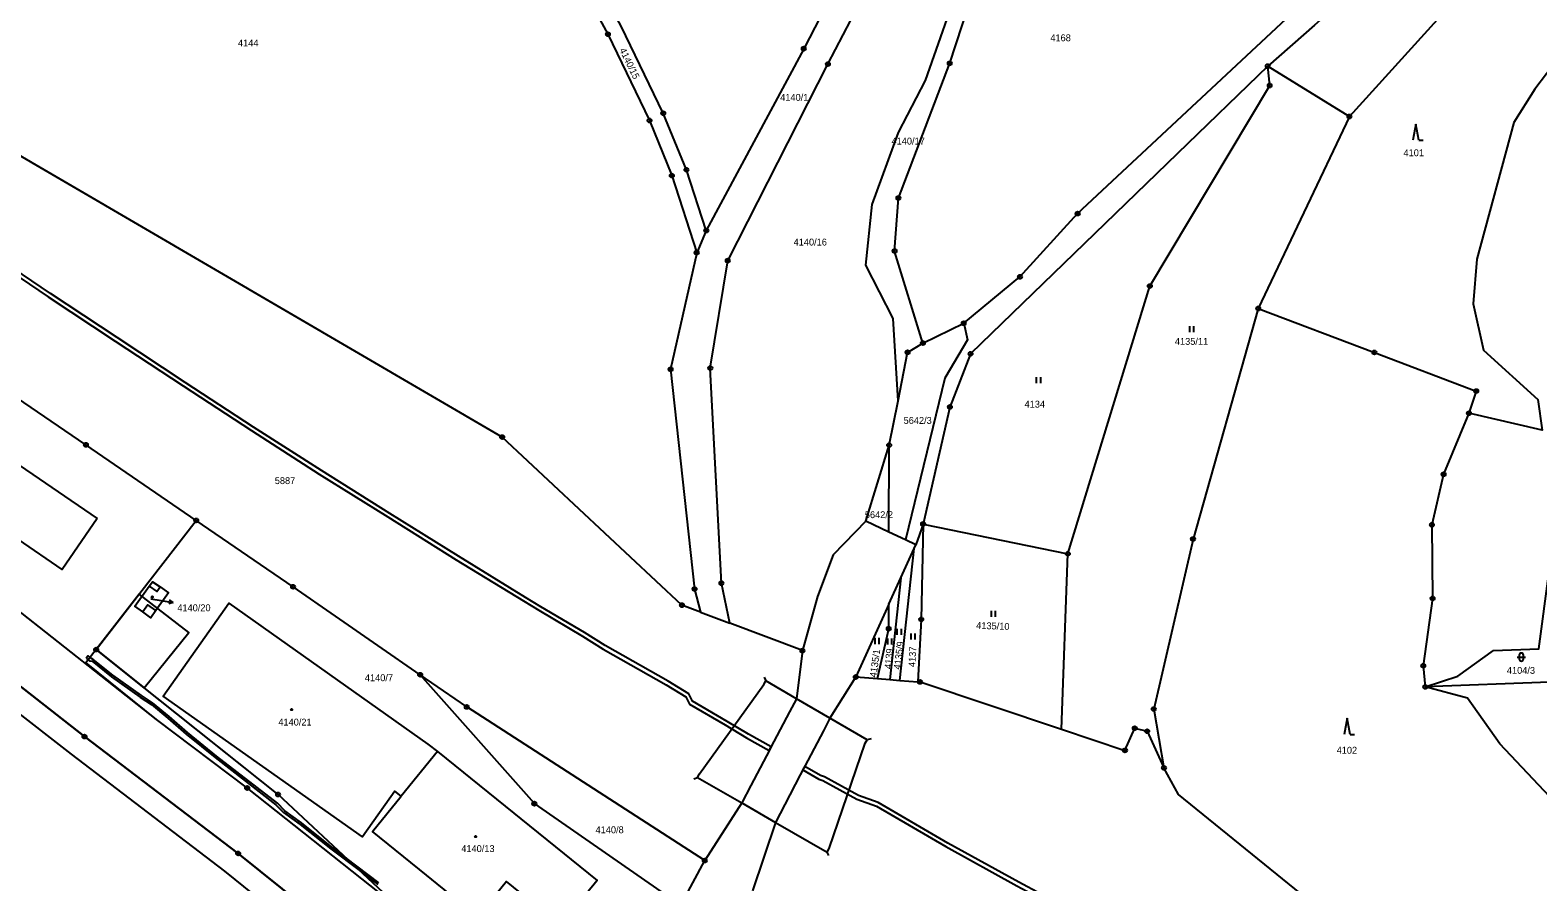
# Model space of a CAD drawing. Extents: x -644096 to -634268, y -1141430 to -1133463.
# Drawn here: x -641187.5 to -640815.2, y -1136928.3 to -1136718.2 of the extents above; entities that cross this region are included whole.
import ezdxf

# ---------------------------------------------------------------- set-up
doc = ezdxf.new("R2010")
doc.units = 0
for name, color, linetype in [('_CIVIL_CONSTRUCTION', 7, 'Continuous'), ('B_Hranice _3D', 7, 'Continuous'), ('M_Svah_Nasyp', 7, 'Continuous'), ('M_Svah_Zarez', 7, 'Continuous'), ('svrsek_osa_sjezdy', 7, 'Continuous'), ('svrsek_osa_VRT', 7, 'Continuous'), ('svrsek_popisy_VRT', 7, 'Continuous'), ('terminal_VRT', 7, 'Continuous')]:
    doc.layers.add(name, color=color, linetype=linetype)

msp = doc.modelspace()

# ---------------------------------------------------------------- linework, layer by layer
at = {"layer": '_CIVIL_CONSTRUCTION'}
for centre, radius in [((-641044.81, -1136719.17), 0.5), ((-641044.81, -1136719.17), 0.0303), ((-640996.46, -1136722.74), 0.5), ((-640996.46, -1136722.74), 0.0303), ((-640990.48, -1136726.55), 0.5), ((-640990.48, -1136726.55), 0.0303), ((-640960.4, -1136726.35), 0.5), ((-640960.4, -1136726.35), 0.0303), ((-640881.86, -1136727.05), 0.5), ((-640881.86, -1136727.05), 0.0303), ((-640881.37, -1136731.83), 0.5), ((-640881.37, -1136731.83), 0.0303), ((-641034.54, -1136740.46), 0.5), ((-641034.54, -1136740.46), 0.0303), ((-641031.14, -1136738.67), 0.5), ((-641031.14, -1136738.67), 0.0303), ((-640861.71, -1136739.47), 0.5), ((-640861.71, -1136739.47), 0.0303), ((-641025.42, -1136752.63), 0.5), ((-641025.42, -1136752.63), 0.0303), ((-641029.02, -1136754.05), 0.5), ((-641029.02, -1136754.05), 0.0303), ((-640973.07, -1136759.6), 0.5), ((-640973.07, -1136759.6), 0.0303), ((-640928.81, -1136763.44), 0.5), ((-640928.81, -1136763.44), 0.0303), ((-641020.51, -1136767.62), 0.5), ((-641020.51, -1136767.62), 0.0303), ((-641022.89, -1136773.08), 0.5), ((-641022.89, -1136773.08), 0.0303), ((-641015.22, -1136775.06), 0.5), ((-641015.22, -1136775.06), 0.0303), ((-640974.02, -1136772.68), 0.5), ((-640974.02, -1136772.68), 0.0303), ((-640943.05, -1136779.05), 0.5), ((-640943.05, -1136779.05), 0.0303), ((-640910.99, -1136781.33), 0.5), ((-640910.99, -1136781.33), 0.0303), ((-640884.2, -1136786.86), 0.5), ((-640884.2, -1136786.86), 0.0303), ((-640956.95, -1136790.5), 0.5), ((-640956.95, -1136790.5), 0.0303), ((-640970.81, -1136797.68), 0.5), ((-640967.02, -1136795.4), 0.5), ((-640967.02, -1136795.4), 0.0303), ((-640855.52, -1136797.7), 0.5), ((-641019.52, -1136801.57), 0.5), ((-640970.81, -1136797.68), 0.0303), ((-640955.26, -1136798.04), 0.5), ((-640955.26, -1136798.04), 0.0303), ((-640855.52, -1136797.7), 0.0303), ((-641029.33, -1136801.85), 0.5), ((-641029.33, -1136801.85), 0.0303), ((-641019.52, -1136801.57), 0.0303), ((-640830.37, -1136807.23), 0.5), ((-640830.37, -1136807.23), 0.0303), ((-640960.36, -1136811.17), 0.5), ((-640960.36, -1136811.17), 0.0303), ((-640832.18, -1136812.7), 0.5), ((-640832.18, -1136812.7), 0.0303), ((-641070.93, -1136818.59), 0.5), ((-641070.93, -1136818.59), 0.0303), ((-641173.71, -1136820.5), 0.5), ((-641173.71, -1136820.5), 0.0303), ((-640975.35, -1136820.59), 0.5), ((-640975.35, -1136820.59), 0.0303), ((-640838.43, -1136827.76), 0.5), ((-640838.43, -1136827.76), 0.0303), ((-641146.48, -1136839.16), 0.5), ((-641146.48, -1136839.16), 0.0303), ((-640966.99, -1136840.04), 0.5), ((-640966.99, -1136840.04), 0.0303), ((-640841.33, -1136840.25), 0.5), ((-640841.33, -1136840.25), 0.0303), ((-640900.32, -1136843.75), 0.5), ((-640900.32, -1136843.75), 0.0303), ((-640931.24, -1136847.39), 0.5), ((-640931.24, -1136847.39), 0.0303), ((-641122.56, -1136855.53), 0.5), ((-641122.56, -1136855.53), 0.0303), ((-641023.42, -1136856.09), 0.5), ((-641023.42, -1136856.09), 0.0303), ((-641016.78, -1136854.64), 0.5), ((-641016.78, -1136854.64), 0.0303), ((-641026.53, -1136860.06), 0.5), ((-641026.53, -1136860.06), 0.0303), ((-640841.16, -1136858.41), 0.5), ((-640841.16, -1136858.41), 0.0303), ((-640967.44, -1136863.59), 0.5), ((-640967.44, -1136863.59), 0.0303), ((-640975.46, -1136865.87), 0.5), ((-640975.46, -1136865.87), 0.0303), ((-641171.19, -1136871.04), 0.5), ((-641171.19, -1136871.04), 0.0303), ((-640996.78, -1136871.28), 0.5), ((-640996.78, -1136871.28), 0.0303), ((-640843.46, -1136875.03), 0.5), ((-640843.46, -1136875.03), 0.0303), ((-641091.18, -1136877.23), 0.5), ((-641091.18, -1136877.23), 0.0303), ((-640983.59, -1136877.79), 0.5), ((-640983.59, -1136877.79), 0.0303), ((-640967.72, -1136879.01), 0.5), ((-640967.72, -1136879.01), 0.0303), ((-640842.96, -1136880.23), 0.5), ((-640842.96, -1136880.23), 0.0303), ((-641079.67, -1136885.18), 0.5), ((-641079.67, -1136885.18), 0.0303), ((-640910.01, -1136885.72), 0.5), ((-640910.01, -1136885.72), 0.0303), ((-640914.71, -1136890.43), 0.5), ((-640914.71, -1136890.43), 0.0303), ((-641174.07, -1136892.51), 0.5), ((-641174.07, -1136892.51), 0.0303), ((-640911.64, -1136891.17), 0.5), ((-640911.64, -1136891.17), 0.0303), ((-640917.12, -1136895.9), 0.5), ((-640917.12, -1136895.9), 0.0303), ((-640907.49, -1136900.22), 0.5), ((-640907.49, -1136900.22), 0.0303), ((-641133.9, -1136905.19), 0.5), ((-641133.9, -1136905.19), 0.0303), ((-641126.26, -1136906.79), 0.5), ((-641126.26, -1136906.79), 0.0303), ((-641062.98, -1136909.05), 0.5), ((-641062.98, -1136909.05), 0.0303), ((-641136.12, -1136921.34), 0.5), ((-641136.12, -1136921.34), 0.0303), ((-641020.89, -1136923.11), 0.5), ((-641020.89, -1136923.11), 0.0303)]:
    msp.add_circle(centre, radius, dxfattribs=at)
at = {"layer": 'B_Hranice _3D'}
for points in [[(-641199.5, -1136772.91), (-641183.01, -1136784.01), (-641166.53, -1136794.89), (-641149.71, -1136805.97), (-641132.85, -1136816.95), (-641116.09, -1136827.7), (-641099.17, -1136838.31), (-641082.25, -1136848.86), (-641065.66, -1136859.01), (-641061.89, -1136861.31), (-641051.1, -1136867.71), (-641045.99, -1136870.9), (-641030.45, -1136879.69), (-641025.57, -1136882.66), (-641024.65, -1136884.48), (-641015.89, -1136889.63), (-641010.59, -1136892.79), (-641007.77, -1136894.33), (-641004.98, -1136895.94), (-641004.51, -1136895.05), (-641007.29, -1136893.45), (-641010.09, -1136891.93), (-641015.39, -1136888.77), (-641023.89, -1136883.76), (-641024.81, -1136881.96), (-641029.95, -1136878.83), (-641045.47, -1136870.04), (-641050.58, -1136866.85), (-641061.37, -1136860.45), (-641065.14, -1136858.15), (-641081.73, -1136848), (-641098.63, -1136837.47), (-641115.55, -1136826.86), (-641132.31, -1136816.11), (-641149.17, -1136805.13), (-641165.97, -1136794.05), (-641182.45, -1136783.17), (-641198.94, -1136772.09)], [(-640932.27, -1136934.34), (-640943.37, -1136928.42), (-640960.83, -1136918.76), (-640978.07, -1136908.79), (-640982.89, -1136907.05), (-640991.35, -1136902.42), (-640992.34, -1136902.08), (-640996.21, -1136899.85), (-640996.67, -1136900.74), (-640992.76, -1136903), (-640991.75, -1136903.34), (-640983.31, -1136907.97), (-640978.49, -1136909.71), (-640961.33, -1136919.64), (-640943.85, -1136929.3), (-640932.75, -1136935.22), (-640926.3, -1136938.9), (-640908.7, -1136948.23), (-640890.7, -1136957.63), (-640873.12, -1136966.73), (-640855.28, -1136975.78), (-640837.3, -1136984.75), (-640819.52, -1136993.48), (-640801.34, -1137002.18)], [(-641101.36, -1136928.56), (-641109.5, -1136922.41), (-641105.94, -1136925.72), (-641101.66, -1136928.96)]]:
    msp.add_lwpolyline(points, dxfattribs=at)
for points in [[(-641263.85, -1136833.08), (-641242.49, -1136847.34), (-641207.87, -1136873.11), (-641177.38, -1136896.86), (-641139.48, -1136925.67), (-641106.26, -1136952.5), (-641103.94, -1136947.21), (-641136.12, -1136921.34), (-641174.07, -1136892.51), (-641204.56, -1136868.74), (-641239.35, -1136842.84), (-641260.66, -1136828.6)], [(-641171.19, -1136871.04), (-641159.31, -1136880.49), (-641148.32, -1136866.85), (-641160.58, -1136857.35)], [(-641173.72, -1136874.3), (-641156.38, -1136888.32), (-641133.9, -1136905.19), (-641094.12, -1136936.74), (-641126.26, -1136906.79), (-641159.31, -1136880.49), (-641171.19, -1136871.04)], [(-641173.63, -1136873.17), (-641172.8, -1136873.79), (-641172.21, -1136873.86), (-641167.38, -1136877.72), (-641160.3, -1136882.76), (-641157.55, -1136884.6), (-641153.46, -1136887.96), (-641148.97, -1136891.91), (-641141.76, -1136897.7), (-641126.78, -1136909.32), (-641124.95, -1136911.23), (-641120.8, -1136914.21), (-641113.25, -1136920.2), (-641105.94, -1136925.72), (-641109.5, -1136922.41), (-641112.95, -1136919.8), (-641120.5, -1136913.81), (-641124.63, -1136910.85), (-641126.44, -1136908.94), (-641141.46, -1136897.3), (-641148.65, -1136891.53), (-641153.14, -1136887.58), (-641157.25, -1136884.2), (-641160.02, -1136882.34), (-641167.08, -1136877.32), (-641171.95, -1136873.44), (-641172.35, -1136873.19), (-641173.18, -1136872.57)]]:
    msp.add_lwpolyline(points, close=True, dxfattribs=at)
at = {"layer": 'M_Svah_Nasyp'}
for p, q in [((-641006.26, -1136877.87), (-641005.82, -1136878.77)), ((-640998.26, -1136883.15), (-641005.82, -1136878.77)), ((-640989.98, -1136887.93), (-640998.26, -1136883.15)), ((-640980.75, -1136893.26), (-640989.98, -1136887.93)), ((-640979.77, -1136893.09), (-640980.75, -1136893.26)), ((-641023.63, -1136902.95), (-641022.71, -1136902.56)), ((-641022.71, -1136902.56), (-641011.76, -1136908.86)), ((-641011.76, -1136908.86), (-641003.42, -1136913.67)), ((-641003.42, -1136913.67), (-640990.7, -1136920.99)), ((-640990.23, -1136921.87), (-640990.7, -1136920.99))]:
    msp.add_line(p, q, dxfattribs=at)
for points in [[(-641158.08, -1136855.36), (-641156.2, -1136856.72), (-641155.4, -1136855.58)], [(-641156.47, -1136861.4), (-641158.42, -1136860), (-641159.67, -1136861.74)], [(-641022.71, -1136902.56), (-641022.21, -1136901.69), (-641006.32, -1136879.63), (-641005.82, -1136878.77)], [(-640990.7, -1136920.99), (-640990.2, -1136920.12), (-640981.25, -1136894.12), (-640980.75, -1136893.26)]]:
    msp.add_lwpolyline(points, dxfattribs=at)
at = {"layer": 'M_Svah_Zarez'}
for centre in [(-641157.33, -1136858.03), (-641122.94, -1136885.82), (-641077.49, -1136917.17)]:
    msp.add_circle(centre, 0.175, dxfattribs=at)
at = {"layer": 'svrsek_osa_sjezdy'}
for p, q in [((-640845.27, -1136741.35), (-640846.02, -1136745.35)), ((-640844.52, -1136745.35), (-640845.27, -1136741.35)), ((-640844.52, -1136745.35), (-640843.52, -1136745.35)), ((-640901.1, -1136792.7), (-640901.1, -1136791.2)), ((-640900.1, -1136792.7), (-640900.1, -1136791.2)), ((-640938.94, -1136805.28), (-640938.94, -1136803.78)), ((-640937.94, -1136805.28), (-640937.94, -1136803.78)), ((-640950.12, -1136862.93), (-640950.12, -1136861.43)), ((-640949.12, -1136862.93), (-640949.12, -1136861.43)), ((-640978.82, -1136869.66), (-640978.82, -1136868.16)), ((-640977.82, -1136869.66), (-640977.82, -1136868.16)), ((-640973.35, -1136867.39), (-640973.35, -1136865.89)), ((-640972.35, -1136867.39), (-640972.35, -1136865.89)), ((-640969.95, -1136868.56), (-640969.95, -1136867.06)), ((-640968.95, -1136868.56), (-640968.95, -1136867.06)), ((-640975.67, -1136869.8), (-640975.67, -1136868.3)), ((-640974.67, -1136869.8), (-640974.67, -1136868.3)), ((-640820.24, -1136872.88), (-640818.24, -1136872.88)), ((-640819.74, -1136872.38), (-640819.74, -1136873.38)), ((-640818.74, -1136873.38), (-640818.74, -1136872.38)), ((-640862.23, -1136887.99), (-640862.98, -1136891.99)), ((-640861.48, -1136891.99), (-640862.23, -1136887.99)), ((-640861.48, -1136891.99), (-640860.48, -1136891.99))]:
    msp.add_line(p, q, dxfattribs=at)
for centre, start, end in [((-640819.24, -1136872.38), 0, 180), ((-640819.24, -1136873.38), 180, 359.9879)]:
    msp.add_arc(centre, 0.5, start, end, dxfattribs=at)
at = {"layer": 'svrsek_popisy_VRT'}
for p, q in [((-641157.68, -1136858.48), (-641155.15, -1136858.91)), ((-641155.15, -1136858.91), (-641152.2, -1136859.43)), ((-641152.2, -1136859.43), (-641153.27, -1136859.75)), ((-641152.2, -1136859.43), (-641153.09, -1136858.76))]:
    msp.add_line(p, q, dxfattribs=at)
at = {"layer": 'terminal_VRT'}
for p, q in [((-640881.86, -1136727.05), (-640861.71, -1136739.47)), ((-640861.71, -1136739.47), (-640884.2, -1136786.86)), ((-641020.51, -1136767.62), (-641022.89, -1136773.08)), ((-640967.02, -1136795.4), (-640956.95, -1136790.5)), ((-640975.35, -1136820.59), (-640973.1, -1136809.65)), ((-640981.08, -1136839.37), (-640975.35, -1136820.59)), ((-640975.4, -1136842.05), (-640975.35, -1136820.59)), ((-640975.4, -1136842.05), (-640981.08, -1136839.37)), ((-640971.32, -1136843.97), (-640975.4, -1136842.05)), ((-640966.99, -1136840.04), (-640968.78, -1136845.17)), ((-640966.99, -1136840.04), (-640931.24, -1136847.39)), ((-640968.78, -1136845.17), (-640971.32, -1136843.97)), ((-640969.18, -1136846.05), (-640968.78, -1136845.17)), ((-640972.48, -1136853.31), (-640969.18, -1136846.05)), ((-640932.82, -1136890.66), (-640931.24, -1136847.39)), ((-640975.45, -1136859.85), (-640972.48, -1136853.31)), ((-640972.48, -1136853.31), (-640975.22, -1136878.43)), ((-640975.45, -1136859.85), (-640983.59, -1136877.79)), ((-641021.98, -1136861.78), (-641014.71, -1136864.52)), ((-640996.78, -1136871.28), (-641014.71, -1136864.52)), ((-640983.59, -1136877.79), (-640978.21, -1136878.2)), ((-640978.21, -1136878.2), (-640975.22, -1136878.43)), ((-640975.22, -1136878.43), (-640972.74, -1136878.62)), ((-640972.74, -1136878.62), (-640968.3, -1136878.97)), ((-640812.31, -1136879.11), (-640842.96, -1136880.23)), ((-641086.91, -1136896.17), (-641095.88, -1136907.22)), ((-641026.83, -1136934.12), (-641020.89, -1136923.11))]:
    msp.add_line(p, q, dxfattribs=at)
for points in [[(-640825.4, -1136677.24), (-640870.35, -1136716.9), (-640881.86, -1136727.05)], [(-640973.1, -1136809.65), (-640974.34, -1136789.33), (-640981.09, -1136776.14), (-640979.53, -1136761.22), (-640973.02, -1136743.42), (-640966.4, -1136730.6), (-640948.09, -1136678.55)], [(-640967.02, -1136795.4), (-640974.02, -1136772.68), (-640973.07, -1136759.6), (-640960.4, -1136726.35), (-640945.05, -1136679.55)], [(-640814.44, -1136685.07), (-640836.78, -1136712.1), (-640861.71, -1136739.47)], [(-640785.47, -1136686.87), (-640810.18, -1136725.16), (-640815.93, -1136732.72), (-640821.1, -1136740.93), (-640830.26, -1136774.68), (-640831.11, -1136785.71), (-640828.55, -1136797.1), (-640815.18, -1136809.28), (-640814.09, -1136816.89), (-640832.18, -1136812.7)], [(-641021.98, -1136861.78), (-641026.53, -1136860.06), (-641070.93, -1136818.59), (-641196.36, -1136745.52), (-641265.5, -1136695.04)], [(-641057.54, -1136696.34), (-641056.64, -1136697.54), (-641044.81, -1136719.17), (-641034.54, -1136740.46), (-641029.02, -1136754.05), (-641022.89, -1136773.08)], [(-641020.51, -1136767.62), (-641025.42, -1136752.63), (-641031.14, -1136738.67), (-641041.5, -1136717.18), (-641053.16, -1136695.94), (-641054.14, -1136694.56)], [(-640984.13, -1136698.91), (-640996.46, -1136722.74), (-641020.51, -1136767.62)], [(-641014.71, -1136864.52), (-641016.78, -1136854.64), (-641019.52, -1136801.57), (-641015.22, -1136775.06), (-640990.48, -1136726.55), (-640977.24, -1136701.11)], [(-640956.95, -1136790.5), (-640943.05, -1136779.05), (-640928.81, -1136763.44), (-640869.89, -1136708.4)], [(-640881.86, -1136727.05), (-640904.14, -1136748.6), (-640955.26, -1136798.04), (-640960.36, -1136811.17), (-640966.99, -1136840.04)], [(-640931.24, -1136847.39), (-640910.99, -1136781.33), (-640881.37, -1136731.83), (-640881.86, -1136727.05)], [(-641146.48, -1136839.16), (-641173.71, -1136820.5), (-641285.97, -1136743.98)], [(-641317.44, -1136774.35), (-641244.29, -1136822.8), (-641214.15, -1136843.74), (-641192.68, -1136859.63), (-641156.38, -1136888.32), (-641133.9, -1136905.19), (-641094.12, -1136936.74)], [(-641022.89, -1136773.08), (-641029.33, -1136801.85), (-641023.42, -1136856.09), (-641021.98, -1136861.78)], [(-641327.67, -1136787.21), (-641273.37, -1136820.11), (-641260.66, -1136828.6), (-641239.35, -1136842.84), (-641204.56, -1136868.74), (-641174.07, -1136892.51), (-641136.12, -1136921.34), (-641103.94, -1136947.21)], [(-640884.2, -1136786.86), (-640900.32, -1136843.75), (-640910.01, -1136885.72), (-640907.49, -1136900.22)], [(-640884.2, -1136786.86), (-640855.52, -1136797.7), (-640830.37, -1136807.23), (-640832.18, -1136812.7)], [(-640956.95, -1136790.5), (-640956.03, -1136794.6), (-640961.63, -1136804.07), (-640971.32, -1136843.97)], [(-640973.1, -1136809.65), (-640970.81, -1136797.68), (-640967.02, -1136795.4)], [(-641170.96, -1136838.64), (-641179.58, -1136851.27), (-641222.76, -1136821.67), (-641214.28, -1136809.16), (-641170.96, -1136838.64)], [(-640842.96, -1136880.23), (-640834.94, -1136877.62), (-640826.15, -1136871.27), (-640814.94, -1136870.88), (-640807.58, -1136815.79), (-640807.16, -1136809.05)], [(-640832.18, -1136812.7), (-640838.43, -1136827.76), (-640841.33, -1136840.25), (-640841.16, -1136858.41), (-640843.46, -1136875.03), (-640842.96, -1136880.23)], [(-641326.4, -1136920.98), (-641263.85, -1136833.08), (-641242.49, -1136847.34), (-641207.87, -1136873.11), (-641177.38, -1136896.86), (-641139.48, -1136925.67), (-641106.26, -1136952.5)], [(-641094.12, -1136936.74), (-641126.26, -1136906.79), (-641171.19, -1136871.04), (-641146.48, -1136839.16)], [(-641091.18, -1136877.23), (-641122.56, -1136855.53), (-641146.48, -1136839.16)], [(-640981.08, -1136839.37), (-640989.16, -1136847.64), (-640993.03, -1136857.91), (-640996.78, -1136871.28)], [(-640966.99, -1136840.04), (-640967.44, -1136863.59), (-640968.3, -1136878.97)], [(-640972.74, -1136878.62), (-640970.76, -1136860.52), (-640969.18, -1136846.05)], [(-641158.08, -1136855.36), (-641157.24, -1136854.28), (-641155.4, -1136855.58), (-641153.36, -1136857.04), (-641156.47, -1136861.4), (-641157.7, -1136863.16), (-641159.67, -1136861.74), (-641161.63, -1136860.34), (-641158.08, -1136855.36)], [(-641095.88, -1136907.22), (-641097.45, -1136905.94), (-641105.45, -1136917.25), (-641154.63, -1136882.5), (-641138.44, -1136859.59), (-641089.27, -1136894.35), (-641086.91, -1136896.17)], [(-640978.21, -1136878.2), (-640975.46, -1136865.87), (-640975.45, -1136859.85)], [(-640996.78, -1136871.28), (-640998.26, -1136883.15), (-640999.95, -1136886.37), (-641003.8, -1136893.69), (-641005.66, -1136897.24), (-641009.5, -1136904.55), (-641011.76, -1136908.86), (-641020.89, -1136923.11)], [(-641026.83, -1136934.12), (-641062.98, -1136909.05), (-641091.18, -1136877.23)], [(-641020.89, -1136923.11), (-641079.67, -1136885.18), (-641091.18, -1136877.23)], [(-640983.59, -1136877.79), (-640989.98, -1136887.93), (-640991.61, -1136891.04), (-640995.46, -1136898.42), (-640997.31, -1136901.97), (-641001.13, -1136909.28), (-641003.42, -1136913.67), (-641009.09, -1136930.57)], [(-640968.3, -1136878.97), (-640967.72, -1136879.01), (-640932.82, -1136890.66)], [(-640791.27, -1136915.24), (-640792.2, -1136927.19), (-640803.98, -1136916.09), (-640824.56, -1136894.31), (-640832.55, -1136883.01), (-640842.96, -1136880.23)], [(-640932.82, -1136890.66), (-640917.12, -1136895.9), (-640914.71, -1136890.43), (-640911.64, -1136891.17), (-640907.49, -1136900.22)], [(-641086.91, -1136896.17), (-641047.48, -1136927.99), (-641056.53, -1136939.03), (-641069.88, -1136928.26), (-641076.92, -1136936.97), (-641089.59, -1136926.73), (-641102.94, -1136915.89), (-641095.88, -1136907.22)], [(-640769.91, -1136991.12), (-640773.25, -1136989.7), (-640812.25, -1136975.25), (-640849.5, -1136950.9), (-640903.92, -1136906.75), (-640907.49, -1136900.22)]]:
    msp.add_lwpolyline(points, dxfattribs=at)

# ---------------------------------------------------------------- texts
at = {"layer": 'svrsek_osa_VRT'}
for s, p in [('4168', (-640935.55, -1136720.91)), ('4144', (-641136.17, -1136722.19)), ('4140/1', (-641002.26, -1136735.61)), ('4140/17', (-640974.77, -1136746.4)), ('4101', (-640848.34, -1136749.28)), ('4140/16', (-640998.95, -1136771.32)), ('4135/11', (-640904.79, -1136795.82)), ('4134', (-640941.92, -1136811.32)), ('5642/3', (-640971.79, -1136815.33)), ('5887', (-641127.08, -1136830.19)), ('5642/2', (-640981.36, -1136838.59)), ('4140/20', (-641151.15, -1136861.57)), ('4104/3', (-640822.81, -1136877.01)), ('4140/7', (-641104.83, -1136878.83)), ('4140/21', (-641126.2, -1136889.78)), ('4102', (-640864.85, -1136896.72)), ('4140/8', (-641047.86, -1136916.35)), ('4140/13', (-641081.02, -1136920.99))]:
    msp.add_text(s, height=1.7, dxfattribs=at).set_placement(p)
for s, rotation, p in [('4140/15', 296, (-641042.03, -1136723.06)), ('4135/10', 358, (-640953.88, -1136865.9)), ('4135/1', 82, (-640978.52, -1136877.97)), ('4139', 85, (-640974.81, -1136875.88)), ('4135/9', 83, (-640972.56, -1136876.03)), ('4137', 87, (-640968.91, -1136875.38))]:
    msp.add_text(s, height=1.7, rotation=rotation, dxfattribs=at).set_placement(p)

doc.saveas('drawing.dxf')
